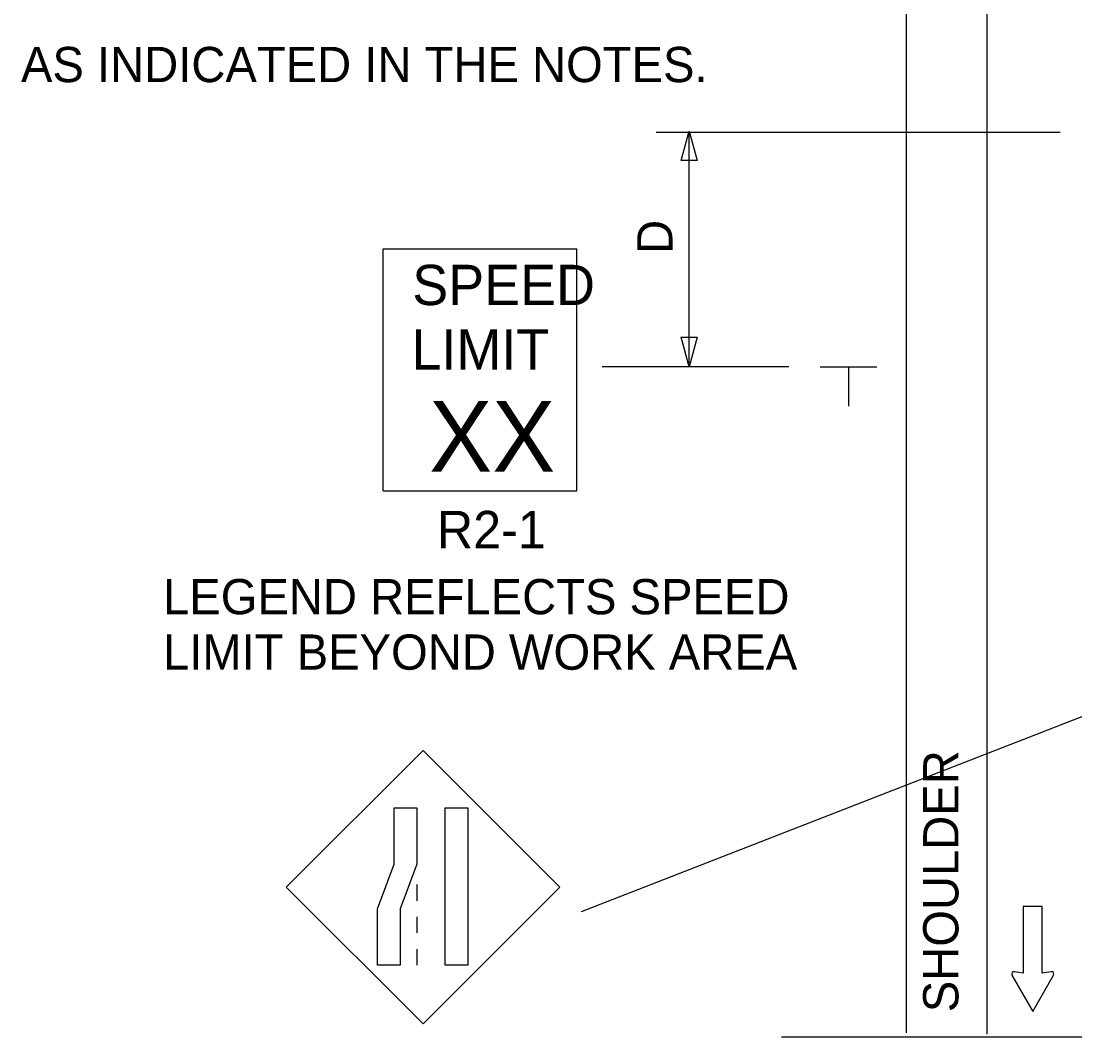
# Model space of a CAD drawing. Extents: x 20837 to 23689, y 414 to 2167.
# Drawn here: x 20937.7 to 21146.9, y 831.4 to 1033.1 of the extents above; entities that cross this region are included whole.
import ezdxf

# ---------------------------------------------------------------- set-up
doc = ezdxf.new("R2010")
doc.units = 0
for name, color, linetype in [('MT_SCRATCH_LEVEL_E', 7, 'Continuous'), ('PAVT_EDGE_EX', 7, 'Continuous'), ('TRAFFIC_SIGNS_PR', 7, 'Continuous'), ('TYPICAL_EX', 7, 'Continuous'), ('TYPICAL_TEXT_DIMEN_PR', 7, 'Continuous')]:
    doc.layers.add(name, color=color, linetype=linetype)

msp = doc.modelspace()

# ---------------------------------------------------------------- linework, layer by layer
at = {"layer": 'MT_SCRATCH_LEVEL_E'}
for p, q in [((21140.37, 857.31), (21136.63, 857.31)), ((21136.63, 857.31), (21136.63, 844.05)), ((21140.37, 857.31), (21136.63, 857.31)), ((21136.63, 857.31), (21136.63, 844.05)), ((21140.37, 844.05), (21140.37, 857.31)), ((21140.37, 844.05), (21140.37, 857.31)), ((21134.37, 843.69), (21138.52, 836.44)), ((21134.37, 843.69), (21138.52, 836.44)), ((21136.63, 844.05), (21134.85, 844.37)), ((21136.63, 844.05), (21134.85, 844.37)), ((21138.52, 836.44), (21142.63, 843.69)), ((21138.52, 836.44), (21142.63, 843.69)), ((21142.15, 844.37), (21140.37, 844.05)), ((21142.15, 844.37), (21140.37, 844.05))]:
    msp.add_line(p, q, dxfattribs=at)
for centre, start, end in [((21134.78, 843.91), 80.0362, 209.7731), ((21134.78, 843.91), 80.0362, 209.7731), ((21142.22, 843.91), 330.4248, 99.9638), ((21142.22, 843.91), 330.4248, 99.9638)]:
    msp.add_arc(centre, 0.463, start, end, dxfattribs=at)
at = {"layer": 'PAVT_EDGE_EX'}
msp.add_line((21129.4, 1637.35), (21129.4, 831.94), dxfattribs=at)
at = {"layer": 'TRAFFIC_SIGNS_PR'}
for p, q in [((21009.59, 987.85), (21047.99, 987.85)), ((21009.59, 939.85), (21009.59, 987.85)), ((21047.99, 939.85), (21047.99, 987.85)), ((21009.59, 939.85), (21047.99, 939.85)), ((21017.52, 888.31), (20990.37, 861.16)), ((21044.68, 861.16), (21017.52, 888.31)), ((20990.37, 861.16), (21017.52, 834.01)), ((21016.28, 861.65), (21016.28, 858.45)), ((21017.52, 834.01), (21044.68, 861.16)), ((21016.28, 855.25), (21016.28, 852.05)), ((21016.28, 848.85), (21016.28, 845.65))]:
    msp.add_line(p, q, dxfattribs=at)
for points in [[(21016.28, 876.9), (21016.28, 865.72), (21012.93, 856.83), (21012.93, 845.65), (21008.44, 845.65), (21008.44, 856.83), (21011.78, 865.72), (21011.78, 876.9)], [(21026.41, 876.9), (21026.41, 845.65), (21021.92, 845.65), (21021.92, 876.9)]]:
    msp.add_lwpolyline(points, close=True, dxfattribs=at)
at = {"layer": 'TYPICAL_EX'}
msp.add_line((21113.4, 1637.05), (21113.4, 832.24), dxfattribs=at)
at = {"layer": 'TYPICAL_TEXT_DIMEN_PR'}
for p, q in [((21143.95, 1010.98), (21063.78, 1010.98)), ((21068.75, 1005.41), (21070.32, 1011.27)), ((21070.32, 1011.27), (21071.89, 1005.41)), ((21070.32, 964.86), (21070.32, 1010.98)), ((21070.32, 1005.41), (21068.75, 1005.41)), ((21071.89, 1005.41), (21070.32, 1005.41)), ((21070.32, 964.46), (21068.75, 970.32)), ((21068.75, 970.32), (21070.32, 970.32)), ((21070.32, 970.32), (21071.89, 970.32)), ((21071.89, 970.32), (21070.32, 964.46)), ((21090.07, 964.46), (21053.08, 964.46)), ((21096.31, 964.42), (21107.56, 964.42)), ((21101.93, 964.42), (21101.93, 956.64)), ((21236.68, 929.44), (21048.91, 856.28)), ((21088.66, 831.41), (21334.82, 831.41))]:
    msp.add_line(p, q, dxfattribs=at)

# ---------------------------------------------------------------- texts
at = {"layer": 'TRAFFIC_SIGNS_PR'}
for s, height, p in [('AS INDICATED IN THE NOTES.', 7, (20937.71, 1020.97)), ('SPEED', 8, (21015.36, 976.71)), ('LIMIT', 8, (21015.2, 963.91)), ('XX', 14.031, (21018.71, 943.61)), ('R2-1', 7.44, (21020.27, 928.41)), ('LEGEND REFLECTS SPEED', 7, (20965.9, 915.32)), ('LIMIT BEYOND WORK AREA', 7, (20965.9, 904.32))]:
    msp.add_text(s, height=height, dxfattribs=at).set_placement(p)
at = {"layer": 'TYPICAL_TEXT_DIMEN_PR'}
for s, p in [('D', (21067.01, 986.87)), ('SHOULDER', (21123.75, 836.32))]:
    msp.add_text(s, height=7, rotation=90, dxfattribs=at).set_placement(p)

doc.saveas('drawing.dxf')
